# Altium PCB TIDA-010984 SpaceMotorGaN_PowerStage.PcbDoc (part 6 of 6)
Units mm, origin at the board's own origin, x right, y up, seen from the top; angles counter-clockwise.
Board outline 177.8 x 152.4 mm, 8 copper layers (Top Layer, DC LINK Layer 2, GND Layer 3, 3V3 Layer 4, Layer 5, Layer 6, GND Layer 7, Bottom Layer), stack 1.554 mm thick; 582 components, 280 nets, 1847 pads, 979 vias.
Unrouted connection lines stored in the file: 474.
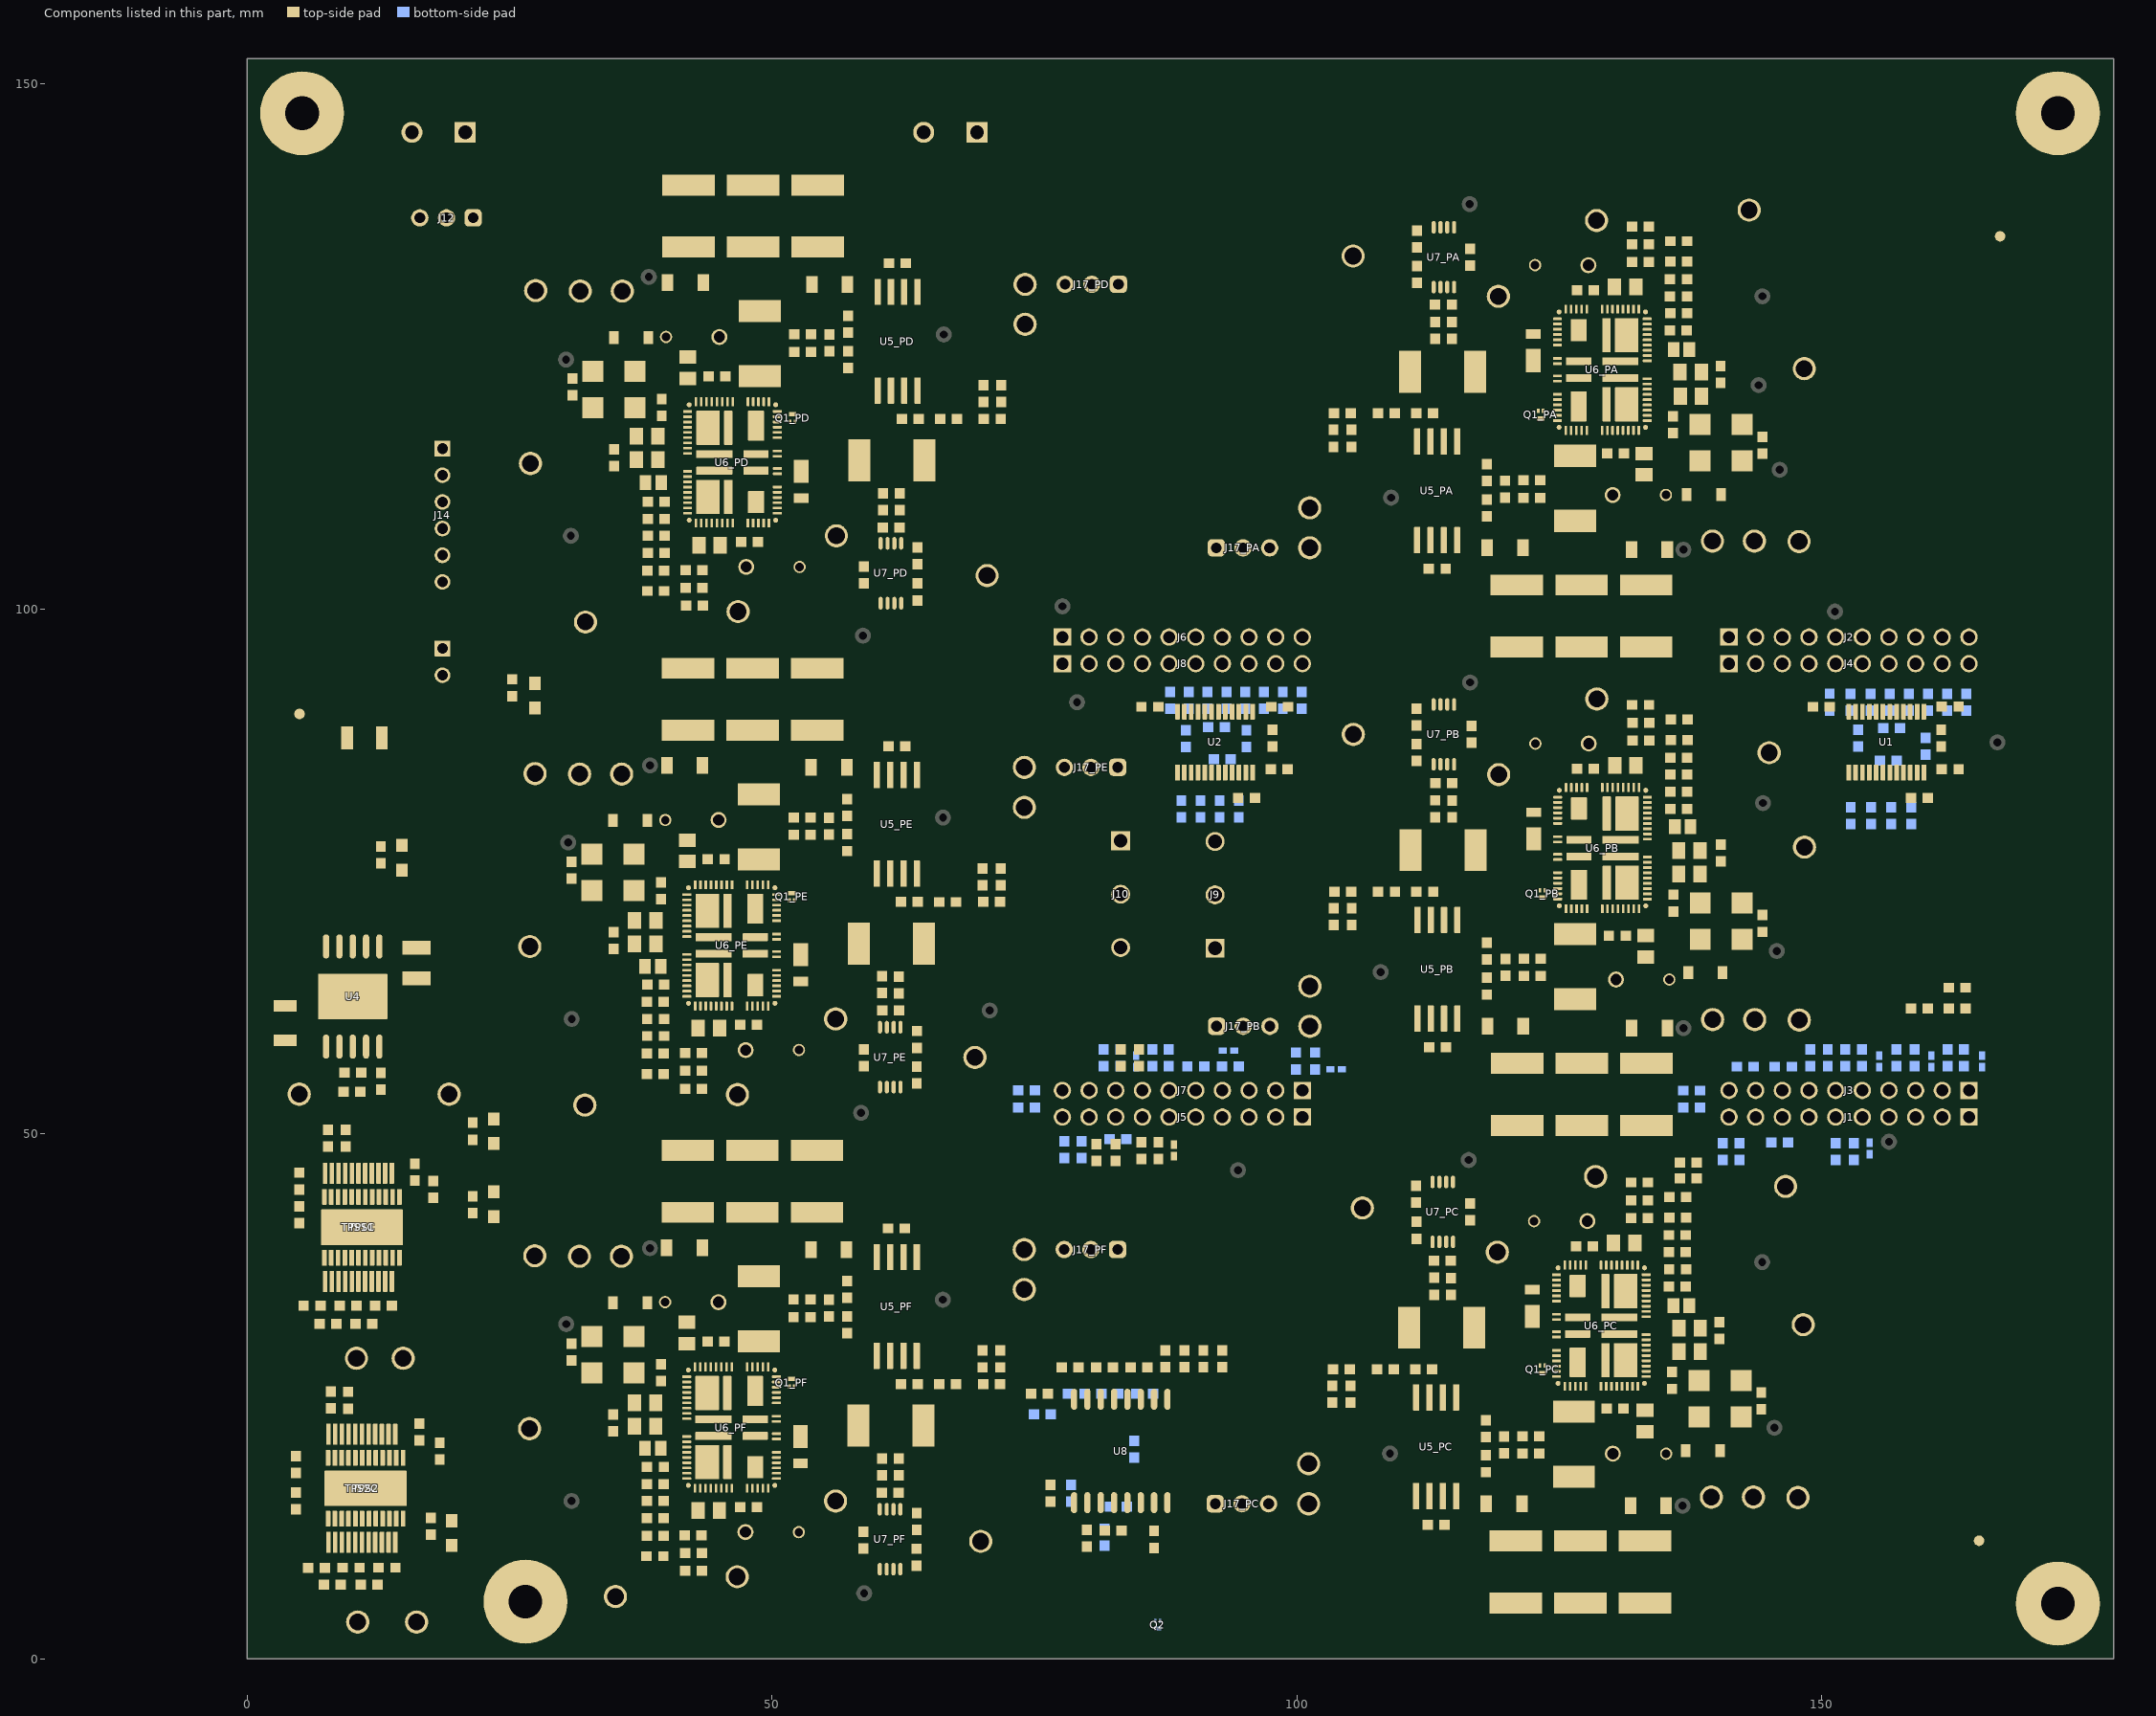
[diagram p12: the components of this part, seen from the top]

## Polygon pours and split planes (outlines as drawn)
GND on Top Layer "TOP_LAYER_GND_P095" (solid, remove dead copper, pour order 95): 1.25,151.15 1.25,151.25 176.75,151.25 176.75,1.25 1.25,1.25 1.25,151.25
VBUS on Top Layer "TOP_LAYER_VBUS_P091" (solid, remove dead copper, pour order 91): 44.72,38.026 42.685,38.026 42.035,40.711 39.299,40.711 39.299,45.497 57.168,45.497 57.168,39.867 54.951,39.867 54.668,38.08 52.721,38.08 51.062,35.612 46.695,35.612
SW_PF on Top Layer "TOP_LAYER_SW_PF_P065" (solid, pour order 65): 58,20.709 58,23.493 45.112,23.493 45.112,28.366 41.189,28.366 41.189,22.03 46.081,22.03 47.131,20.709
HVIN_PF on Top Layer "TOP_LAYER_HVIN_PF_P069" (solid, remove dead copper, pour order 69): 46.701,31.254 50.809,31.254 50.809,23.619 50.683,23.493 46.701,23.493
VBUS on Top Layer "TOP_LAYER_VBUS_P072" (solid, remove dead copper, pour order 72): 110.679,83.171 108.644,83.171 107.994,85.855 105.258,85.855 105.258,90.642 123.127,90.642 123.127,85.011 120.91,85.011 120.627,83.225 118.68,83.225 117.021,80.757 112.654,80.757
HVIN_PC on Top Layer "TOP_LAYER_HVIN_PC_P089" (solid, remove dead copper, pour order 89): 128.467,22.498 124.359,22.498 124.359,30.133 124.485,30.259 128.467,30.259
VBUS on Top Layer "TOP_LAYER_VBUS_P087" (solid, remove dead copper, pour order 87): 130.448,15.726 132.483,15.726 133.133,13.041 135.869,13.041 135.869,8.255 118,8.255 118,13.885 120.217,13.885 120.5,15.672 122.447,15.672 124.106,18.14 128.473,18.14
SW_PC on Top Layer "TOP_LAYER_SW_PC_P085" (solid, pour order 85): 117.25,33.079 117.25,30.259 130.056,30.259 130.056,25.386 133.979,25.386 133.979,33.079
HVIN_PB on Top Layer "TOP_LAYER_HVIN_PB_P084" (solid, remove dead copper, pour order 84): 128.587,67.984 124.479,67.984 124.479,75.62 124.605,75.746 128.587,75.746
VBUS on Top Layer "TOP_LAYER_VBUS_P082" (solid, remove dead copper, pour order 82): 130.569,61.213 132.603,61.213 133.253,58.528 135.99,58.528 135.99,53.742 118.12,53.742 118.12,59.372 120.337,59.372 120.62,61.158 122.567,61.158 124.226,63.627 128.593,63.627
SW_PB on Top Layer "TOP_LAYER_SW_PB_P080" (solid, pour order 80): 117.37,78.566 117.37,75.746 130.177,75.746 130.177,70.873 134.099,70.873 134.099,78.566
HVIN_PA on Top Layer "TOP_LAYER_HVIN_PA_P079" (solid, remove dead copper, pour order 79): 128.565,113.553 124.457,113.553 124.457,121.189 124.583,121.315 128.565,121.315
VBUS on Top Layer "TOP_LAYER_VBUS_P077" (solid, remove dead copper, pour order 77): 130.546,106.782 132.581,106.782 133.231,104.097 135.967,104.097 135.967,99.31 118.098,99.31 118.098,104.941 120.315,104.941 120.598,106.727 122.545,106.727 124.204,109.196 128.571,109.196
SW_PA on Top Layer "TOP_LAYER_SW_PA_P075" (solid, pour order 75): 117.348,124.135 117.348,121.315 130.154,121.315 130.154,116.442 134.077,116.442 134.077,124.135
HVIN_PB on Top Layer "TOP_LAYER_HVIN_PB_P074" (solid, remove dead copper, pour order 74): 112.66,76.399 116.768,76.399 116.768,68.763 116.642,68.637 112.66,68.637
HVIN_PE on Top Layer "TOP_LAYER_HVIN_PE_P064" (solid, remove dead copper, pour order 64): 46.709,77.179 50.823,77.179 50.823,69.543 50.697,69.417 46.709,69.417
VBUS on Top Layer "TOP_LAYER_VBUS_P062" (solid, remove dead copper, pour order 62): 44.733,83.95 42.699,83.95 42.049,86.635 39.312,86.635 39.312,91.421 57.182,91.421 57.182,85.791 54.965,85.791 54.682,84.005 52.735,84.005 51.076,81.536 46.709,81.536
SW_PE on Top Layer "TOP_LAYER_SW_PE_P060" (solid, pour order 60): 58,66.633 58,69.417 45.125,69.417 45.125,74.29 41.203,74.29 41.203,67.954 46.094,67.954 47.145,66.633
SW_PD on Top Layer "TOP_LAYER_SW_PD_P005" (solid, pour order 5): 58,112.609 58,115.429 45.194,115.429 45.194,120.302 41.271,120.302 41.271,112.609
VBUS on Top Layer "TOP_LAYER_VBUS_P008" (solid, remove dead copper, pour order 8): 44.802,129.962 42.767,129.962 42.117,132.647 39.381,132.647 39.381,137.433 57.25,137.433 57.25,131.803 55.033,131.803 54.75,130.016 52.803,130.016 51.144,127.548 46.777,127.548
HVIN_PD on Top Layer "TOP_LAYER_HVIN_PD_P059" (solid, remove dead copper, pour order 59): 46.783,123.191 50.891,123.191 50.891,115.555 50.765,115.429 46.783,115.429
12Vp on Top Layer "TOP_LAYER_12VP_P050" (solid, remove dead copper, pour order 50): 9.755,22.439 9.803,22.392 13.692,22.392 13.692,18.392 9.771,18.392 9.771,22.345 9.818,22.392
3V3 on Top Layer "TOP_LAYER_3V3_P049" (solid, remove dead copper, pour order 49): 13.915,14.142 14.005,5.931 14.012,5.278 11.859,5.278 11.341,5.615 11.341,9.268 11.096,9.514 10.002,9.514 10.002,14.142
12Vp on Top Layer "TOP_LAYER_12VP_P048" (solid, remove dead copper, pour order 48): 9.407,47.297 9.454,47.25 13.343,47.25 13.343,43.25 9.422,43.25 9.422,47.203 9.469,47.25
5V on Top Layer "TOP_LAYER_5V_P047" (solid, remove dead copper, pour order 47): 13.434,39 13.434,32.065 12.619,31.25 10.993,31.25 10.993,34.126 10.747,34.372 9.779,34.372 9.779,39
3V3 on 3V3 Layer 4 "3V3_LAYER_4_3V3_P055" (solid, remove dead copper, pour order 55): 1.25,151.15 1.25,151.25 176.75,151.25 176.75,1.25 1.25,1.25 1.25,151.25
GND on GND Layer 3 "GND_LAYER_3_GND_P094" (solid, remove dead copper, pour order 94): 1.25,151.15 1.25,151.25 176.75,151.25 176.75,1.25 1.25,1.25 1.25,151.25
VBUS on DC LINK Layer 2 "DC_LINK_LAYER_2_VBUS_P058" (solid, remove dead copper, pour order 58): 1.25,151.15 1.25,151.25 176.75,151.25 176.75,1.25 1.25,1.25 1.25,151.25
GND on GND Layer 7 "GND_LAYER_7_GND_P056" (solid, remove dead copper, pour order 56): 1.305,151.162 1.305,151.262 176.805,151.262 176.805,1.262 1.305,1.262 1.305,151.262

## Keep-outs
Keep-Out Layer:
  text ".Layer_Name" at 14.656,-21.806 h1.52

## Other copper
Top Layer:
  region: -15.925,66.5
  region: -15.925,66.5
  region: -15.925,66.5
  region: -15.925,66.5
  region: -15.925,66.5
  region: -15.925,66.5
  region: -15.925,66.5
  region: -15.925,66.5
  region: -15.925,66.5
  region: -15.925,66.5
  region: -15.925,66.5
  region: -15.925,66.5
  region: -15.925,66.5
  region: -15.925,66.5
  region: -15.925,66.5
  region: -15.925,66.5
  region: -15.925,66.5
  region: -15.925,66.5
  region: -15.925,66.5
  region: -15.925,66.5
  region: -15.925,66.5
  region: -15.925,66.5
  region: -15.925,66.5
  region: -15.925,66.5
  region: -15.925,66.5
  region: -15.925,66.5
  region: -15.925,66.5
  region: -15.925,66.5
  region: -15.925,66.5
  region: -15.925,66.5
  region: -15.925,66.5
  region: -15.925,66.5
  region: -15.925,66.5
  region: -15.925,66.5
  region: -15.925,66.5
  region: -15.925,66.5
  region: -15.925,66.5
  region: -15.925,66.5
  region: -15.925,66.5
  region: -15.925,66.5
  region: -15.925,66.5
  region: -15.925,66.5
  region: -15.925,66.5
  region: -15.925,66.5
  region: -15.925,66.5
  region: -15.925,66.5
  region: -15.925,66.5
  region: -15.925,66.5
  region: -15.925,66.5
  region: -15.925,66.5
  region: -15.925,66.5
  region: -15.925,66.5
  region: -8.777,63.66
  region: -8.777,63.66
  region: -8.777,63.66
  region: -8.777,63.66
  region: -8.777,63.66
  region: -8.777,63.66
  region: -8.777,63.66
  region: -8.777,63.66
  region: -8.777,63.66
  region: -8.777,63.66
  region: -8.777,63.66
  region: -8.777,63.66
  region: -8.777,63.66
  region: -8.777,63.66
  region: -8.777,63.66
  region: -8.777,63.66
  region: -8.777,63.66
  region: -8.777,63.66
  region: -8.777,63.66
  region: -8.777,63.66
  region: -8.777,63.66
  region: -8.777,63.66
  region: -8.777,63.66
  region: -8.777,63.66
  region: -8.777,63.66
  region: -8.777,63.66
  region: -8.777,63.66
  region: -8.777,63.66
  region: -8.777,63.66
  region: -8.777,63.66
  region: -8.777,63.66
  region: -8.777,63.66
  region: -8.777,63.66
  region: -8.777,63.66
  region: -8.777,63.66
  region: -8.777,63.66
  region: -8.777,63.66
  region: -8.777,63.66
  region: -8.777,63.66
  region: -8.777,63.66
  region: -8.777,63.66
  region: -8.777,63.66
  region: -8.777,63.66
  region: -8.777,63.66
  region: -8.777,63.66
  region: -8.777,63.66
  region: -8.777,63.66
  region: -8.777,63.66
  region: -8.777,63.66
  region: -8.777,63.66
  region: -8.777,63.66
  region: -8.777,63.66
  text ".Layer_Name" at 14.656,-21.806 h1.52
Bottom Layer:
  text ".Layer_Name" at 14.656,-21.806 h1.52

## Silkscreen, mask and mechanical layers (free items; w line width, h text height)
Top Overlay:
  circle w0.254: c59.987,26.734 r0.155
  circle w0.254: c60.001,72.659 r0.155
  circle w0.254: c60.069,118.671 r0.155
  circle w0.254: c115.279,118.073 r0.155
  circle w0.254: c115.301,72.504 r0.155
  circle w0.254: c115.181,27.017 r0.155
  circle w0.254: c166.473,56.287 r0.253
  circle w0.254: c166.473,49.537 r0.253
  circle w0.254: c102.831,49.298 r0.253
  circle w0.254: c102.682,56.25 r0.253
  circle w0.254: c75.5,92.5 r0.253
  circle w0.254: c75.437,99.345 r0.253
  circle w0.254: c139.024,92.5 r0.253
  circle w0.254: c138.885,99.31 r0.253
  region: 163.084,56.372 164.862,56.372 163.973,55.483
  region: 164.862,49.352 163.084,49.352 163.973,50.241
  region: 101.389,49.298 99.611,49.298 100.5,50.187
  region: 99.611,56.372 101.389,56.372 100.5,55.483
  lines w0.076: 97.111,59.024 97.111,56.372 98,55.483 98.889,56.372 98.889,59.09 97.111,59.09 ; 164.925,99.989 164.925,103.037 ; 164.925,99.989 164.036,99.1 163.147,99.989 163.147,103.037 164.925,103.037 ; 164.925,99.989 164.925,103.037 ; 99.823,99.31 100.712,98.421 101.601,99.31 101.601,102.358 99.823,102.358 99.823,99.31 ; 160.607,56.702 160.607,59.75 162.385,59.75 162.385,56.702 161.496,55.813 160.607,56.702
  lines w0.152: 56.016,123.5 56.141,121.953 56.141,121.616 56.5,121.257 ; 57.943,122.103 58.111,121.934 58.111,121.357 ; 58.076,128.651 58.75,130.016 ; 63.076,107.063 63.636,107.063 64.369,107.634 ; 64.25,119.14 65,119.984
  lines w0.254: 0.5,84.75 20.525,84.777 20.525,128.592 0.5,128.5 ; 40.563,79.269 41.808,80.514 ; 40.563,80.543 41.817,79.269 ; 40.85,33.42 42.095,34.666 ; 40.85,34.694 42.104,33.42 ; 41.024,125.524 42.269,126.769 ; 41.024,126.798 42.278,125.524 ; 44.75,11.81 44.75,11.783 46.255,10.278 47.172,10.278 48.7,8.75 49.73,8.75 ; 44.764,57.734 44.764,57.708 46.269,56.202 47.186,56.202 48.714,54.674 49.743,54.674 ; 44.832,103.746 44.832,103.72 46.338,102.214 47.254,102.214 48.782,100.686 49.812,100.686 ; 57.943,122.103 57.943,122.226 ; 117,24.53 117,23.769 117.307,23.462 ; 117.405,114.517 117.405,115.329 ; 117.428,68.948 117.428,69.76 ; 118.68,70.07 119,69.75 119,69.73 119.511,69.22 119.511,67.518 ; 118.75,24.629 119.057,24.322 119.057,24.28 119.057,21.884 ; 118.948,115 118.965,115 119.206,114.759 119.206,112.99 ; 125.438,45.002 126.468,45.002 127.996,43.474 128.912,43.474 130.418,41.969 130.418,41.942 ; 125.536,136.058 126.566,136.058 128.094,134.53 129.01,134.53 130.516,133.024 130.516,132.998 ; 125.558,90.48 126.588,90.48 128.116,88.952 129.033,88.952 130.538,87.447 130.538,87.42 ; 132.936,110.229 134.181,111.474 ; 132.936,111.502 134.19,110.229 ; 132.966,18.911 134.211,20.157 ; 132.966,20.185 134.22,18.911 ; 133.189,65.539 133.259,65.539 134.513,64.265 ; 133.259,64.265 134.504,65.51 134.504,65.539 ; 14.559,129.75 17.353,129.75 17.353,135.764 14.559,135.764 14.559,129.75 ; 17.35,92.147 19.89,92.147 19.89,97.727 17.35,97.727 17.35,92.147 ; 17.35,101.037 17.35,116.777 19.89,116.777 19.89,101.037 17.35,101.037 ; 17.654,129.75 20.448,129.75 20.448,135.764 17.654,135.764 17.654,129.75 ; 20.729,129.75 23.523,129.75 23.523,135.764 20.729,135.764 20.729,129.75
  lines w0.635: 14.775,150.75 16.275,150.75 ; 19.855,150.75 21.355,150.75 ; 20.605,150 20.605,151.5 ; 63.525,150.75 65.025,150.75 ; 68.605,150.75 70.105,150.75 ; 69.355,150 69.355,151.5
  text "This document can handle board shapes up to 7.9in x 10in, although" at 7.276,218.788 h1.52
  text "our panel vendors top out at 7in x 10in." at 7.276,215.637 h1.52
  text "To re-size the board shape, do the following:" at 8.673,212.486 h1.52
  text "Select lines on M1 Board Outline and delete (easy in single layer mode...shift+s)" at 10.197,209.335 h1.52
  text "Draw a rectangle using lines (example will be for a 4\" x 6\" board" at 10.197,206.184 h1.52
  text "Enter Place Line mode (keyboard pl)" at 15.466,203.145 h1.52
  text "keyboard jo to jump to origin, hit enter" at 15.466,199.993 h1.52
  text "keyboard jl to jump to location, set x to 6000, hit enter twice" at 15.531,196.731 h1.52
  text "Hit ESC twice to exit place line mode" at 8.642,193.727 h1.52
  text "keyboard jl to jump to location, set x to 0 and y to 4000, hit enter twice" at 8,191.25 h1.52
  text "keyboard jo to jump to origin, hit enter" at 15.466,187.389 h1.52
  text "keyboard jl to jump to location, set x to 6000 and y to 4000, hit enter twice" at 15.25,184.25 h1.52
  text "Select lines on M1 Board Outline" at 7.947,180.467 h1.52
  text "Menu Design|Board Shape|Define from Selected Objects (keyboard dsd)" at 10.197,177.824 h1.52
  text "If you re-size the board, don't forget to move the drill table strings on the" at 7.276,169.716 h1.52
  text "Drill Drawing Layer...they should be just to the right of your board shape" at 12.178,167.023 h1.52
  text "VBUS in" at 74.25,149.75 h1.52
  text "28VDC (15-36VDC)" at 25,147.5 h1.52
  text "GND" at 119.75,139.067 h0.76 r180
  text "VBUS" at 19.483,131.001 h1.52 r90
  text "28VDC" at 16.733,130.499 h1.52 r90
  text "VBUS in" at 22.483,130.251 h1.52 r90
  text "GND" at 147.75,130.25 h0.76 r180
  text "PMP23546" at 13.032,127.322 h2.54 r270
  text "GND" at 66.014,123.985 h0.76
  text "GND" at 27,123.236 h0.76
  text "GND" at 149.626,113.857 h0.76 r180
  text "GND" at 109.397,112.778 h0.76 r180
  text "GND" at 27.673,107.984 h0.76
  text "GND" at 164.544,102.529 h0.97 r90
  text "GND" at 151.776,101.885 h0.76 r180
  text "GND" at 101.008,101.85 h0.97 r90
  text "GND" at 75.652,101.402 h0.76
  text "GND" at 55.5,97.75 h0.76
  text "GND" at 119.848,93.348 h0.76 r180
  text "12Vs" at 28.71,90.976 h1.52
  text "GND" at 77.872,89.146 h0.76
  text "GND" at 170.336,87.73 h0.76 r180
  text "GND" at 147.62,81.952 h0.76 r180
  text "VA   VB   VC" at 97.496,80.282 h2.54 r270
  text "GND" at 65.827,77.82 h0.76
  text "GND" at 26.932,76.987 h0.76
  text "12Vp" at 16,75.188 h1.52
  text "GND" at 148.952,68.03 h0.76 r180
  text "GND" at 108.848,67.278 h0.76 r180
  text "VF   VE   VD" at 78.007,65.218 h2.54 r90
  text "GND" at 69.152,63.152 h0.76
  text "GND" at 27.682,60.556 h0.76
  text "GND" at 161.981,58.966 h0.97 r90
  text "GND" at 98.5,58.845 h0.97 r90
  text "5V" at 101.389,56.372 h1.52 r90
  text "5V" at 164.862,56.372 h1.52 r90
  text "GND" at 54.999,51.683 h0.76
  text "2V" at 25,49.564 h1.52
  text "GND" at 119.75,48 h0.76 r180
  text "GND" at 158.336,47.93 h0.76 r180
  text "3V3" at 164.862,46.304 h1.52 r90
  text "3V3" at 101.389,46.25 h1.52 r90
  text "GND" at 93.201,44.584 h0.76
  text "5V" at 25,42.386 h1.52
  text "GND" at 147.62,38.25 h0.76 r180
  text "GND" at 65.813,31.896 h0.76
  text "GND" at 26.75,31.254 h0.76
  text "GND" at 149,22.67 h0.76 r180
  text "GND" at 109.413,21.63 h0.76 r180
  text "GND" at 27.355,14.415 h0.76
  text "3V3" at 20.75,11.81 h1.52
  text "GND" at 55.226,5.629 h0.76
  text "'.PRJ_Number'.PCB_Rev" at 52.75,3.25 h2.75
  text ".Layer_Name" at 14.656,-21.806 h1.52
Bottom Overlay:
  circle w0.254: c22.25,48 r0.031
  circle w0.254: c166.5,56.25 r0.253
  circle w0.254: c166.5,49.5 r0.253
  region: 166.702,53.5 166.702,55.278 165.813,54.389
  region: 102.443,54.988 102.443,53.21 101.554,54.099
  region: 166.702,51 166.702,52.778 165.813,51.889
  region: 102.443,50.667 102.443,52.445 101.554,51.556
  lines w0.076: 97.111,56.372 97.111,59.09 98.889,59.068 98.889,56.372 98,55.483 97.111,56.372 ; 99.68,99.678 99.68,102.395 101.458,102.374 101.458,99.678 100.569,98.789 99.68,99.678 ; 160.431,59.872 161.32,58.983 162.209,59.872 162.209,62.568 160.431,62.59 160.431,59.872 ; 163.18,99.928 163.18,102.645 164.958,102.624 164.958,99.928 164.069,99.039 163.18,99.928
  text "GND" at 164.569,102.425 h0.97 r90
  text "GND" at 101,102 h0.97 r90
  text "GND" at 161.82,62.369 h0.97 r90
  text "GND" at 98.508,58.524 h0.97 r90
  text "5V" at 169.75,53.5 h1.52
  text "5V" at 105.5,53.21 h1.52
  text "3V3" at 169.75,51 h1.52
  text "3V3" at 105.5,50.667 h1.52
  text ".Layer_Name" at 14.656,-21.806 h1.52
Top Paste:
  text ".Layer_Name" at 14.656,-21.806 h1.52
Bottom Paste:
  text ".Layer_Name" at 14.656,-21.806 h1.52
Top Solder:
  text ".Layer_Name" at 14.656,-21.806 h1.52
  text ".Layer_Name" at 14.656,-21.806 h1.52
Bottom Solder:
  text ".Layer_Name" at 14.656,-21.806 h1.52
Drill Guide:
  text ".Layer_Name" at 14.656,-21.806 h1.52
M1 Board Outline:
  the board outline again, w0.254
  text ".Layer_Name" at 14.656,-21.806 h1.52
M2 Board Dimensions:
  rectangle: 0,-6.985 3.175,-3.81
  rectangle: 3.175,-10.16 12.7,-6.985
  lines w0.178: 0,-6.985 25.4,-6.985 ; 3.175,-10.16 3.175,-3.81 ; 6.35,-10.16 6.35,-3.81 ; 12.7,-10.16 12.7,-3.81 ; 19.05,-10.16 19.05,-3.81 ; 0,-10.16 25.4,-10.16 25.4,-3.81 0,-3.81 0,-10.16
  lines w0.254: 0,-0.504 0,0.004 ; 1.523,0.26 0,-0.25 ; 1.525,-0.756 0,-0.25 ; 78.695,-0.139 0,-0.25 ; 98.805,-0.111 177.5,0 ; 175.975,0.506 177.5,0 ; 175.977,-0.51 177.5,0 ; 176.994,1.525 177.5,0 ; 177.24,150.977 177.75,152.5 ; 177.246,0 177.754,0 ; 177.496,152.5 178.004,152.5 ; 177.5,0.254 177.5,-0.254 ; 177.609,66.195 177.5,0 ; 177.641,86.305 177.75,152.5 ; 178.01,1.523 177.5,0 ; 178.256,150.975 177.75,152.5
  text "152.50021 (mm)" at 178.523,66.447 h1.52 r89.91
  text "177.50018 (mm)" at 78.95,-1.053 h1.52 r0.08
  text ".Layer_Name" at 14.656,-21.806 h1.52
M3 3D STEP Top:
  text ".Layer_Name" at 14.656,-21.806 h1.52
M4 3D STEP Bottom:
  text ".Layer_Name" at 14.656,-21.806 h1.52
M5 Assembly Top:
  lines w0.254: -7.417,-23.626 160.223,-23.626 ; -7.417,-18.462 160.274,-18.462 ; -7.417,-13.297 -7.417,-28.791 94.31,-28.791 160.274,-28.791 160.274,-13.297 -7.404,-13.297 -7.404,-28.791 32.614,-28.791 ; 55.194,-28.791 55.194,-13.297 ; 87.376,-18.462 87.376,-13.297 ; 108.712,-18.462 108.712,-13.297 ; 124.511,-28.956 124.511,-23.804
  text "COMPONENTS MARKED 'DNP' SHOULD NOT BE POPULATED." at 29.299,-8.09 h1.52
  text "ASSEMBLY VARIANT:" at 29.286,-11.024 h1.52
  text ".VariantName" at 55.601,-11.024 h1.52
  text "PCB VIEWED FROM TOP SIDE" at -5.804,-16.654 h1.52
  text "BOARD #:" at 57.099,-16.654 h1.52
  text ".PRJ_Number" at 70.955,-16.654 h1.52
  text "REV:" at 92.405,-16.654 h1.52
  text ".PCB_Rev" at 99.809,-16.654 h1.52
  text "SVN REV:" at 113.69,-16.654 h1.52
  text ".VersionControl_RevNumber" at 126.543,-16.654 h1.52
  text "TID #:" at 57.099,-21.819 h1.52
  text ".TID" at 70.955,-21.819 h1.52
  text "PLOT NAME =" at -5.804,-27.034 h1.52
  text ".plot_File_Name" at 14.656,-27.034 h1.52
  text "GENERATED    :" at 57.15,-27.034 h1.52
  text ".Print_Date" at 79.235,-27.034 h1.52
  text ".Print_Time" at 97.752,-27.034 h1.52
  text "TEXAS INSTRUMENTS" at 129.87,-27.034 h1.52
M6 Assembly Bottom:
  lines w0.254: -7.429,-18.474 160.261,-18.474 ; -7.379,-23.639 160.261,-23.639 ; 28.334,-28.969 28.334,-23.817 ; 44.133,-18.474 44.133,-13.31 ; 65.468,-18.474 65.468,-13.31 ; 97.65,-28.804 97.65,-13.31 ; 120.231,-28.804 160.249,-28.804 160.249,-13.31 -7.429,-13.31 -7.429,-28.804 58.534,-28.804 160.261,-28.804 160.261,-13.31
  text "COMPONENTS MARKED 'DNP' SHOULD NOT BE POPULATED." at 154.991,-8.077 h1.52
  text ".VariantName" at 128.473,-11.024 h1.52
  text "ASSEMBLY VARIANT:" at 154.864,-11.024 h1.52
  text ".VersionControl_RevNumber" at 26.302,-16.667 h1.52
  text "SVN REV:" at 39.154,-16.667 h1.52
  text ".PCB_Rev" at 53.035,-16.667 h1.52
  text "REV:" at 60.439,-16.667 h1.52
  text ".PRJ_Number" at 81.89,-16.667 h1.52
  text "BOARD #:" at 95.745,-16.667 h1.52
  text "PCB VIEWED FROM BOTTOM SIDE" at 158.648,-16.667 h1.52
  text ".TID" at 81.89,-21.831 h1.52
  text "TID #:" at 95.745,-21.831 h1.52
  text "TEXAS INSTRUMENTS" at 22.974,-27.047 h1.52
  text ".Print_Time" at 55.093,-27.047 h1.52
  text ".Print_Date" at 73.609,-27.047 h1.52
  text "GENERATED    :" at 95.694,-27.047 h1.52
  text ".plot_File_Name" at 138.189,-27.047 h1.52
  text "PLOT NAME =" at 158.648,-27.047 h1.52
M9 Title Sheet:
  drawing of 57 lines, arcs and shapes, not listed
  text "1" at 18.792,204.127 h1.78
  text "2" at 82.182,204.127 h1.78
  text "3" at 145.411,204.127 h1.78
  text "4" at 209.08,204.127 h1.78
  text "5" at 272.555,204.127 h1.78
  text "6" at 336.182,204.127 h1.78
  text "A" at -10.579,175.095 h1.78
  text "A" at 365.341,175.095 h1.78
  text "B" at -10.579,114.643 h1.78
  text "B" at 365.341,114.643 h1.78
  text "C" at -10.579,54.318 h1.78
  text "C" at 365.341,54.318 h1.78
  text "PROJECT TITLE:" at 288.125,7.048 h1.14
  text ".PRJ_Title" at 289.395,3.662 h1.78
  text "DESIGNED FOR:" at 288.125,-0.597 h1.14
  text ".PRJ_Customer" at 289.395,-4.153 h1.78
  text "D" at -10.579,-5.88 h1.78
  text "D" at 365.341,-5.88 h1.78
  text "FILE NAME:" at 288.125,-8.217 h1.14
  text ".PCB_File_Name_No_Path" at 289.395,-11.265 h1.78
  text "Texas Instruments (TI) and/or its licensors do not warrant the accuracy or completeness of this specification" at 161.9,-15.376 h1.14
  text "ENGINEER:" at 288.125,-15.583 h1.14
  text "LAYOUT BY:" at 326.352,-15.583 h1.14
  text "or any information contained therein. TI and/or its licensors do not warrant that this design will meet" at 160.757,-18.237 h1.14
  text ".PRJ_Engineer" at 289.395,-19.52 h1.78
  text ".PCB_Layout" at 327.635,-19.52 h1.78
  text "the specifications, will be suitable for your application or fit for any particular purpose, or will operate in" at 160.757,-21.099 h1.14
  text ".Layer_Name" at 14.656,-21.806 h1.52
  text "ALTIUM DESIGNER VERSION:" at 326.352,-23.457 h1.14
  text "an implementation. TI and/or its licensors do not warrant that the design is production worthy. You should" at 160.757,-23.961 h1.14
  text "completely validate and test your design implementation to confirm the system functionality for your application." at 161.9,-26.822 h1.14
  text ".print_Scale" at 289.395,-26.843 h1.78
  text ".Application_BuildNumber" at 327.635,-26.843 h1.78
  text "1" at 18.792,-32.093 h1.78
  text "2" at 82.182,-32.093 h1.78
  text "3" at 145.411,-32.093 h1.78
  text "4" at 209.08,-32.093 h1.78
  text "5" at 272.555,-32.093 h1.78
  text "6" at 336.182,-32.093 h1.78
M10 Fab Notes:
  drawing of 189 lines, arcs and shapes, not listed
  text "DESIGN INFORMATION" at 314.503,161.447 h1.52
  text "MIN. TRACK WIDTH:" at 298.131,158.091 h1.52
  text "8" at 325.976,158.091 h1.52
  text "MIL" at 329.907,158.091 h1.52
  text "7.874" at 321.75,155 h1.52
  text "MIN. CLEARANCE:" at 298.131,154.938 h1.52
  text "MIL" at 329.907,154.938 h1.52
  text "MIN. VIA PAD SIZE:" at 298.131,151.785 h1.52
  text "24" at 325.214,151.785 h1.52
  text "MIL" at 329.907,151.785 h1.52
  text "0.05mm (2MIL)" at 315.784,148.486 h1.52
  text "MINIMUM ANNULAR RING" at 289.769,148.277 h1.52
  text "EXTERNAL" at 333.768,148.277 h1.52
  text "PER" at 294.849,145.48 h1.52
  text "IPC-D-275 CLASS 2 LEVEL C" at 300.437,145.48 h1.52
  text "MIL, HOLES" at 338.238,142.928 h1.52
  text "+/-" at 328.27,142.709 h1.52
  text "+/-" at 349.961,142.709 h1.52
  text "REGISTRATION TOLERANCES:" at 289.769,142.682 h1.52
  text "METAL" at 320.243,142.682 h1.52
  text "5" at 334.879,142.683 h1.52
  text "3" at 356.037,142.683 h1.52
  text "MIL" at 358.99,142.682 h1.52
  text "HOLE SIZE TOLERANCE (UNLESS OTHERWISE SPECIFIED):" at 289.769,140.185 h1.52
  text "+/-" at 349.961,140.112 h1.52
  text "3" at 356.037,140.085 h1.52
  text "MIL" at 358.99,140.085 h1.52
  text "MATERIAL:" at 287.87,136.589 h1.52
  text "FR-4 High Tg" at 312.926,133.324 h1.52
  text "X" at 309.257,133.122 h1.52
  text "FR-4" at 298.563,133.007 h1.52
  text "OTHER" at 336.358,133.007 h1.52
  text "ANSI IPC-6012 TYPE 3 CLASS 2" at 193.484,130.949 h1.52
  text "X" at 185.065,129.987 h1.52
  text "62 MIL (1.6mm) +/-10%" at 306.694,129.374 h1.52
  text "X" at 303.643,129.312 h1.52
  text "THICKNESS:" at 289.769,129.165 h1.52
  text "OTHER" at 339.33,129.165 h1.52
  text "TOLERANCE:" at 289.769,125.652 h1.52
  text "OTHER +/-" at 192.742,124.099 h1.52
  text "ANSI IPC-6012 TYPE 3 CLASS 2" at 194.793,123.033 h1.52
  text "X" at 187.13,122.275 h1.52
  text "BOW & TWIST:" at 289.769,118.302 h1.52
  text "OTHER +/-" at 194.793,116.057 h1.52
  text "DRILLING:" at 287.87,111.258 h1.52
  text "NC_DRILL FILES" at 211.557,110.068 h1.52
  text "X" at 208.306,109.968 h1.52
  text "X" at 182.278,109.207 h1.52
  text "REFERENCE:" at 289.769,108.486 h1.52
  text "AS SHOWN" at 185.705,108.234 h1.52
  text "OTHER" at 219.126,106.355 h1.52
  text "X" at 197.655,106.265 h1.52
  text "20-30 um" at 200.906,106.265 h1.52
  text "PTH COPPER THICKNESS:" at 289.761,104.783 h1.52
  text "BOARD FINISH:" at 287.87,101.034 h1.52
  text "X" at 195.098,99.719 h1.52
  text "TOP" at 198.069,99.719 h1.52
  text "X" at 208.052,99.719 h1.52
  text "BOTTOM" at 211.049,99.719 h1.52
  text "SILKSCREEN:" at 291.812,98.237 h1.52
  text "X" at 195.072,95.777 h1.52
  text "WHITE" at 198.069,95.777 h1.52
  text "OTHER" at 211.049,95.777 h1.52
  text "SILKSCREEN COLOR:" at 291.812,94.295 h1.52
  text "X" at 198.4,92.133 h1.52
  text "GREEN" at 201.397,92.133 h1.52
  text "OTHER" at 217.094,92.133 h1.52
  text "SOLDER RESIST COLOR:" at 291.812,90.477 h1.52
  text "X" at 198.4,88.215 h1.52
  text "MATTE" at 201.397,88.215 h1.52
  text "SEMI-GLOSS" at 217.082,88.199 h1.52
  text "IMMERSION GOLD (ENIG)" at 193.777,83.827 h1.52
  text "ENEPIG" at 227.75,83.644 h1.52
  text "X" at 186.114,82.86 h1.52
  text "SURFACE FINISH:" at 287.87,82.136 h1.52
  text "IMM. TIN/SILVER OR EQUIV" at 296.24,78.649 h1.52
  text "OTHER" at 207.321,78.297 h1.52
  text "ARRAY/PANEL:" at 287.87,74.602 h1.52
  text "CUT AND TRIM PER M1 BOARD OUTLINE" at 189.541,74.141 h1.52
  text "N.C. ROUTE" at 314.819,70.94 h1.52
  text "X" at 332.295,70.94 h1.52
  text "V. SCORE" at 336.816,70.94 h1.52
  text "CERTIFICATION:" at 287.87,67.66 h1.52
  text "MATERIALS AND WORKMANSHIP FOR ALL PCBS" at 306.285,67.66 h1.52
  text "TO MEET OR EXCEED THE REQUIREMENTS OF:" at 306.285,65.271 h1.52
  text "X" at 297.078,62.003 h1.52
  text "ANSI IPC-A-600F CLASS ->" at 300.329,62.003 h1.52
  text "X" at 342.188,62.003 h1.52
  text "2" at 344.982,62.003 h1.52
  text "1" at 336.981,61.965 h1.52
  text "3" at 353.973,61.965 h1.52
  text "X" at 317.702,58.252 h1.52
  text "RoHS" at 320.953,58.252 h1.52
  text "OTHER" at 337.321,58.252 h1.52
  text "PER ORDER" at 347.407,58.252 h1.52
  text ".Layer_Name" at 181.906,55.194 h1.52
  text "ALL BOARDS MUST MEET OR EXCEED UL94-V0 REQUIREMENTS." at 288.569,54.345 h1.52
  text "PCB MUST BEAR THE UL94V-0 UL REGISTERED MATERIAL ID NUMBER" at 288.569,51.397 h1.52
  text "ADDITIONAL REQUIREMENTS:" at 287.87,47.094 h1.52
  text "MICROSECTION:" at 289.769,44.373 h1.52
  text "YES" at 312.775,44.373 h1.52
  text "REQUIRED" at 334.657,40.707 h1.52
  text "BARE BOARD ELEC. TEST:" at 289.769,40.634 h1.52
  text "NONE" at 322.935,40.634 h1.52
  text "X" at 331.66,40.634 h1.52
  text "PER ORDER" at 349.693,40.634 h1.52
  text "XX MIL VIAS REQUIRE NON-CONDUCTIVE FILL AND PLANARIZE" at 294.04,35.428 h1.5
  text "XX MIL VIAS REQUIRE CONDUCTIVE FILL AND PLANARIZE" at 294.243,32.787 h1.52
  text "OUTER XX MIL TRACES REQUIRE 50 OHM SINGLE-ENDED IMPEDANCE" at 294.218,28.637 h1.47
  text "LAYER 2 & 3 (INNER LAYERS) XX MIL WIDE, XX MIL SPACE / TRACES REQUIRE 100 OHM DIFFERENTIAL IMPEDANCE" at 294.015,22.65 h1.52
M11 Gerber Information:
  lines w0.254: -7.417,-23.626 160.223,-23.626 ; -7.417,-18.462 160.274,-18.462 ; -7.417,-13.297 -7.417,-28.791 94.31,-28.791 160.274,-28.791 160.274,-13.297 -7.404,-13.297 -7.404,-28.791 32.614,-28.791 ; 55.194,-28.791 55.194,-13.297 ; 87.376,-18.462 87.376,-13.297 ; 108.712,-18.462 108.712,-13.297 ; 124.511,-28.956 124.511,-23.804
  text "ALL ARTWORK VIEWED FROM TOP SIDE" at -5.804,-16.654 h1.52
  text "BOARD #:" at 57.099,-16.654 h1.52
  text ".PRJ_Number" at 70.955,-16.654 h1.52
  text "REV:" at 92.405,-16.654 h1.52
  text ".PCB_Rev" at 99.809,-16.654 h1.52
  text "SVN REV:" at 113.69,-16.654 h1.52
  text ".VersionControl_RevNumber" at 126.543,-16.654 h1.52
  text "LAYER NAME =" at -5.804,-21.806 h1.52
  text "TID #:" at 57.099,-21.819 h1.52
  text ".TID" at 70.955,-21.819 h1.52
  text "PLOT NAME =" at -5.804,-27.034 h1.52
  text ".plot_File_Name" at 14.656,-27.034 h1.52
  text "GENERATED    :" at 57.15,-27.034 h1.52
  text ".Print_Date" at 79.235,-27.034 h1.52
  text ".Print_Time" at 97.752,-27.034 h1.52
  text "TEXAS INSTRUMENTS" at 129.87,-27.034 h1.52
M12 Stackup:
  drawing of 503 lines, arcs and shapes, not listed
  text "Layer" at 169.547,198.684 h1.52
  text "Name" at 179.959,198.684 h1.52
  text "Material" at 205.606,198.684 h1.52
  text "Thickness" at 227.444,198.684 h1.52
  text "Constant" at 243.95,198.684 h1.52
  text "Board Layer Stack" at 258.424,198.684 h1.52
  text "Top Overlay" at 179.959,195.636 h1.52
  text "Top Solder" at 179.959,192.588 h1.52
  text "Solder Resist" at 205.606,192.588 h1.52
  text "0.40mil" at 227.444,192.588 h1.52
  text "3.5" at 243.95,192.588 h1.52
  text "1" at 169.547,189.54 h1.52
  text "Top Layer" at 179.959,189.54 h1.52
  text "CF-004" at 205.606,189.54 h1.52
  text "1.38mil" at 227.444,189.54 h1.52
  text "Dielectric 1" at 179.959,186.492 h1.52
  text "PP-006" at 205.606,186.492 h1.52
  text "2.80mil" at 227.444,186.492 h1.52
  text "4.1" at 243.95,186.492 h1.52
  text "2" at 169.547,183.444 h1.52
  text "DC LINK Layer 2" at 179.959,183.444 h1.52
  text "CF-004" at 205.606,183.444 h1.52
  text "1.38mil" at 227.444,183.444 h1.52
  text "Dielectric 2" at 179.959,180.396 h1.52
  text "PP-006" at 205.606,180.396 h1.52
  text "2.80mil" at 227.444,180.396 h1.52
  text "4.1" at 243.95,180.396 h1.52
  text "3" at 169.547,177.348 h1.52
  text "GND Layer 3" at 179.959,177.348 h1.52
  text "CF-004" at 205.606,177.348 h1.52
  text "1.38mil" at 227.444,177.348 h1.52
  text "Dielectric 8" at 179.959,174.3 h1.52
  text "PP-006" at 205.606,174.3 h1.52
  text "2.80mil" at 227.444,174.3 h1.52
  text "4.1" at 243.95,174.3 h1.52
  text "4" at 169.547,171.252 h1.52
  text "3V3 Layer 4" at 179.959,171.252 h1.52
  text "CF-004" at 205.606,171.252 h1.52
  text "1.38mil" at 227.444,171.252 h1.52
  text "Dielectric 4" at 179.959,168.204 h1.52
  text "FR-4 High Tg" at 205.606,168.204 h1.52
  text "33.38mil" at 227.444,168.204 h1.52
  text "4.8" at 243.95,168.204 h1.52
  text "5" at 169.547,165.156 h1.52
  text "Layer 5" at 179.959,165.156 h1.52
  text "CF-004" at 205.606,165.156 h1.52
  text "1.38mil" at 227.444,165.156 h1.52
  text "Dielectric 5" at 179.959,162.108 h1.52
  text "PP-006" at 205.606,162.108 h1.52
  text "2.80mil" at 227.444,162.108 h1.52
  text "4.1" at 243.95,162.108 h1.52
  text "6" at 169.547,159.06 h1.52
  text "Layer 6" at 179.959,159.06 h1.52
  text "CF-004" at 205.606,159.06 h1.52
  text "1.38mil" at 227.444,159.06 h1.52
  text "Dielectric 6" at 179.959,156.012 h1.52
  text "PP-006" at 205.606,156.012 h1.52
  text "2.80mil" at 227.444,156.012 h1.52
  text "4.1" at 243.95,156.012 h1.52
  text "7" at 169.547,152.964 h1.52
  text "GND Layer 7" at 179.959,152.964 h1.52
  text "CF-004" at 205.606,152.964 h1.52
  text "1.38mil" at 227.444,152.964 h1.52
  text "Dielectric 7" at 179.959,149.916 h1.52
  text "PP-006" at 205.606,149.916 h1.52
  text "2.80mil" at 227.444,149.916 h1.52
  text "4.1" at 243.95,149.916 h1.52
  text "8" at 169.547,146.868 h1.52
  text "Bottom Layer" at 179.959,146.868 h1.52
  text "CF-004" at 205.606,146.868 h1.52
  text "1.38mil" at 227.444,146.868 h1.52
  text "Bottom Solder" at 179.959,143.82 h1.52
  text "Solder Resist" at 205.606,143.82 h1.52
  text "0.40mil" at 227.444,143.82 h1.52
  text "3.5" at 243.95,143.82 h1.52
  text "Bottom Overlay" at 179.959,140.772 h1.52
  text ".Layer_Name" at 14.656,-21.806 h1.52
M13 Component Bodies Top:
  text ".Layer_Name" at 14.656,-21.806 h1.52
M14 Component Bodies Bottom:
  text ".Layer_Name" at 14.656,-21.806 h1.52
M15 Courtyards Top:
  text ".Layer_Name" at 14.656,-21.806 h1.52
M16 Courtyards Bottom:
  text ".Layer_Name" at 14.656,-21.806 h1.52
Drill Drawing:
  circle w0.254: c181.209,30.714 r0.421
  circle w0.254: c181.209,30.714 r0.702
  circle w0.254: c181.209,11.768 r0.702
  lines w0.254: 180.508,6.154 181.911,6.154 181.209,4.751 180.508,6.154 ; 180.508,7.909 181.911,7.909 181.911,9.312 180.508,9.312 180.508,7.909 ; 180.508,14.224 181.209,14.575 181.911,14.224 181.56,14.926 181.911,15.628 181.209,15.277 180.508,15.628 180.859,14.926 180.508,14.224 ; 180.508,17.382 181.911,17.382 181.911,18.785 180.508,18.785 180.508,17.382 ; 180.508,21.943 181.911,21.943 181.209,20.54 180.508,21.943 ; 180.508,23.697 180.508,24.048 180.859,24.399 180.508,24.75 180.508,25.101 180.859,25.101 181.209,24.75 181.56,25.101 181.911,25.101 181.911,24.75 181.56,24.399 181.911,24.048 181.911,23.697 181.56,23.697 181.209,24.048 180.859,23.697 180.508,23.697 ; 180.508,27.206 180.859,27.206 181.209,26.855 181.56,27.206 181.911,27.206 181.56,27.557 181.911,27.908 181.56,27.908 181.209,28.258 180.859,27.908 180.508,27.908 180.859,27.557 180.508,27.206 ; 180.508,33.872 181.209,33.171 181.911,33.872 181.209,34.574 180.508,33.872 ; 180.508,36.679 180.859,36.679 181.209,36.328 181.56,36.679 181.911,36.679 181.56,37.03 181.911,37.381 181.56,37.381 181.209,37.732 180.859,37.381 180.508,37.381 180.859,37.03 180.508,36.679 ; 180.508,39.837 180.859,39.837 180.859,39.486 181.56,39.486 181.56,39.837 181.911,39.837 181.911,40.539 181.56,40.539 181.56,40.889 180.859,40.889 180.859,40.539 180.508,40.539 180.508,39.837 ; 180.788,5.874 181.631,5.874 181.209,5.032 180.788,5.874 ; 180.788,17.663 181.631,17.663 181.631,18.505 180.788,18.505 180.788,17.663 ; 180.788,27.346 180.999,27.346 181.209,27.136 181.42,27.346 181.631,27.346 181.42,27.557 181.631,27.767 181.42,27.767 181.209,27.978 180.999,27.767 180.788,27.767 180.999,27.557 180.788,27.346
  lines w0.305: 179.235,3.804 261.315,3.804 ; 179.235,41.696 261.315,41.696 ; 187.817,0.646 187.817,44.854 ; 196.25,0.646 196.25,44.854 ; 212.419,0.646 212.419,44.854 ; 219.001,0.646 219.001,44.854 ; 228.53,0.646 228.53,44.854 ; 246.928,0.646 246.928,44.854 ; 179.235,0.646 261.315,0.646 261.315,44.854 179.235,44.854 179.235,0.646
  text "Symbol" at 181.13,42.644 h1.83
  text "Quantity" at 188.764,42.644 h1.83
  text "Finished Hole Size" at 197.197,42.644 h1.83
  text "Plated" at 213.366,42.644 h1.83
  text "Hole Type" at 219.948,42.644 h1.83
  text "Drill Layer Pair" at 229.477,42.644 h1.83
  text "Hole Tolerance" at 247.875,42.644 h1.83
  text "651" at 188.764,39.486 h1.52
  text "7.87mil (0.200mm)" at 197.197,39.486 h1.52
  text "PTH" at 213.366,39.486 h1.52
  text "Round" at 219.948,39.486 h1.52
  text "Top Layer - Bottom Layer" at 229.477,39.486 h1.52
  text "281" at 188.764,36.328 h1.52
  text "8.00mil (0.203mm)" at 197.197,36.328 h1.52
  text "PTH" at 213.366,36.328 h1.52
  text "Round" at 219.948,36.328 h1.52
  text "Top Layer - Bottom Layer" at 229.477,36.328 h1.52
  text "26" at 188.764,33.171 h1.52
  text "16.00mil (0.406mm)" at 197.197,33.171 h1.52
  text "PTH" at 213.366,33.171 h1.52
  text "Round" at 219.948,33.171 h1.52
  text "Top Layer - Bottom Layer" at 229.477,33.171 h1.52
  text "6" at 188.764,30.013 h1.52
  text "28.00mil (0.711mm)" at 197.197,30.013 h1.52
  text "PTH" at 213.366,30.013 h1.52
  text "Round" at 219.948,30.013 h1.52
  text "Top Layer - Bottom Layer" at 229.477,30.013 h1.52
  text "38" at 188.764,26.855 h1.52
  text "30.00mil (0.762mm)" at 197.197,26.855 h1.52
  text "PTH" at 213.366,26.855 h1.52
  text "Round" at 219.948,26.855 h1.52
  text "Top Layer - Bottom Layer" at 229.477,26.855 h1.52
  text "12" at 188.764,23.697 h1.52
  text "32.00mil (0.813mm)" at 197.197,23.697 h1.52
  text "PTH" at 213.366,23.697 h1.52
  text "Round" at 219.948,23.697 h1.52
  text "Top Layer - Bottom Layer" at 229.477,23.697 h1.52
  text "44" at 188.764,20.54 h1.52
  text "40.00mil (1.016mm)" at 197.197,20.54 h1.52
  text "PTH" at 213.366,20.54 h1.52
  text "Round" at 219.948,20.54 h1.52
  text "Top Layer - Bottom Layer" at 229.477,20.54 h1.52
  text "12" at 188.764,17.382 h1.52
  text "42.00mil (1.067mm)" at 197.197,17.382 h1.52
  text "PTH" at 213.366,17.382 h1.52
  text "Round" at 219.948,17.382 h1.52
  text "Top Layer - Bottom Layer" at 229.477,17.382 h1.52
  text "80" at 188.764,14.224 h1.52
  text "45.28mil (1.150mm)" at 197.197,14.224 h1.52
  text "PTH" at 213.366,14.224 h1.52
  text "Round" at 219.948,14.224 h1.52
  text "Top Layer - Bottom Layer" at 229.477,14.224 h1.52
  text "10" at 188.764,11.066 h1.52
  text "51.18mil (1.300mm)" at 197.197,11.066 h1.52
  text "PTH" at 213.366,11.066 h1.52
  text "Round" at 219.948,11.066 h1.52
  text "Top Layer - Bottom Layer" at 229.477,11.066 h1.52
  text "66" at 188.764,7.909 h1.52
  text "63.00mil (1.600mm)" at 197.197,7.909 h1.52
  text "PTH" at 213.366,7.909 h1.52
  text "Round" at 219.948,7.909 h1.52
  text "Top Layer - Bottom Layer" at 229.477,7.909 h1.52
  text "4" at 188.764,4.751 h1.52
  text "125.98mil (3.200mm)" at 197.197,4.751 h1.52
  text "PTH" at 213.366,4.751 h1.52
  text "Round" at 219.948,4.751 h1.52
  text "Top Layer - Bottom Layer" at 229.477,4.751 h1.52
  text "1230 Total" at 188.764,1.593 h1.52
  text ".Layer_Name" at 14.656,-21.806 h1.52
M17 Embedded Cavity:
  text ".Layer_Name" at 14.656,-21.806 h1.52
M18 Embedded Assembly:
  text ".Layer_Name" at 14.656,-21.806 h1.52
M19 Embedded Keepout:
  text ".Layer_Name" at 14.656,-21.806 h1.52

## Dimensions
0,-10.16 to 25.4,-10.16 on M2 Board Dimensions
0,0 to 0,152.4 on M2 Board Dimensions
0,0 to 177.8,0 on M2 Board Dimensions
